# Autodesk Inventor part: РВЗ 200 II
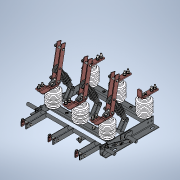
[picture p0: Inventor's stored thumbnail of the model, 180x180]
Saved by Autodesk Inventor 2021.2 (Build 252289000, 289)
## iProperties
Created: 1900-01
Part Number: РВЗ 200 II
Material: Типовые
Description: STEP AP242
Document SubType Name: Modeling
Designer: pc
Density: 1 g/cm^3
Appearance: По умолчанию
Company: UNSPECIFIED
Title: ÐÂÇ 200 II
Author: UNSPECIFIED
Revision Number: ANYUNSPECIFIED
Sending System: C3D Toolkit
Preprocessor: C3D Converter
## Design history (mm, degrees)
feature "БазТело1"
feature "БазТело2"
feature "БазТело3"
feature "БазТело4"
feature "БазТело5"
feature "БазТело6"
feature "БазТело7"
feature "БазТело8"
feature "БазТело9"
feature "БазТело10"
feature "Составной1"
node "Твердое тело1"
node "Твердое тело2"
node "Твердое тело3"
node "Твердое тело4"
node "Твердое тело5"
node "Твердое тело6"
node "Твердое тело7"
node "Твердое тело8"
node "Твердое тело9"
node "Твердое тело10"
body "SRF1"
